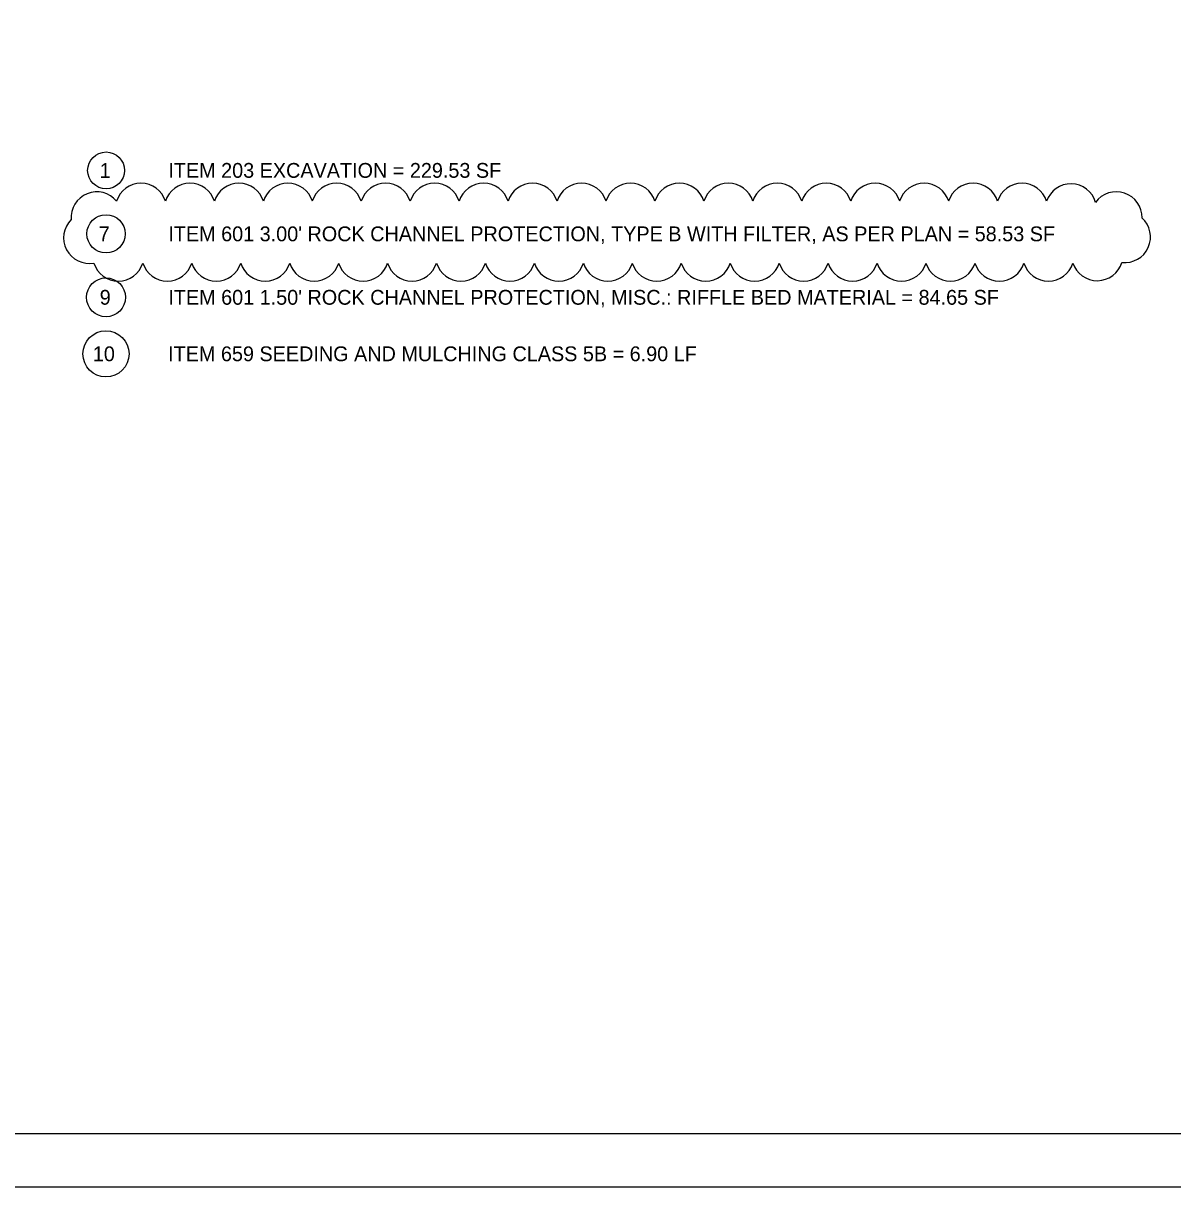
# Model space of a CAD drawing. Extents: x -179 to 34, y 0 to 22.
# Drawn here: x 12.98 to 23.85, y 0 to 11 of the extents above; entities that cross this region are included whole.
import ezdxf

# ---------------------------------------------------------------- set-up
doc = ezdxf.new("R2010")
doc.units = 0
for name, color, linetype in [('CS-ALGN-TEXT', 7, 'Continuous'), ('CS-ANNO', 7, 'Continuous'), ('CS-ANNO-MATC', 7, 'Continuous'), ('CS-ANNO-MATC-TEXT', 7, 'Continuous')]:
    doc.layers.add(name, color=color, linetype=linetype)

msp = doc.modelspace()

# ---------------------------------------------------------------- linework, layer by layer
at = {"layer": 'CS-ALGN-TEXT'}
for centre, radius, start, end in [((14.093, 9.244), 0.243, 17.5, 162.5), ((14.556, 9.244), 0.243, 17.5, 162.5), ((15.019, 9.244), 0.243, 17.5, 162.5), ((15.482, 9.244), 0.243, 17.5, 162.5), ((15.944, 9.244), 0.243, 17.5, 162.5), ((16.407, 9.244), 0.243, 17.5, 162.5), ((16.87, 9.244), 0.243, 17.5, 162.5), ((17.333, 9.244), 0.243, 17.5, 162.5), ((17.796, 9.244), 0.243, 17.5, 162.5), ((18.259, 9.244), 0.243, 17.5, 162.5), ((18.722, 9.244), 0.243, 17.5, 162.5), ((19.185, 9.244), 0.243, 17.5, 162.5), ((19.648, 9.244), 0.243, 17.5, 162.5), ((20.11, 9.244), 0.243, 17.5, 162.5), ((20.573, 9.244), 0.243, 17.5, 162.5), ((21.036, 9.244), 0.243, 17.5, 162.5), ((21.499, 9.244), 0.243, 17.5, 162.5), ((21.962, 9.244), 0.243, 17.5, 162.5), ((22.425, 9.244), 0.243, 17.5, 162.5), ((22.886, 9.239), 0.243, 16.1856, 161.1856), ((13.675, 9.163), 0.243, 39.6166, 184.6166), ((23.316, 9.164), 0.243, 359.0424, 144.0424), ((13.605, 8.972), 0.243, 135.1922, 280.1922), ((23.397, 8.979), 0.242, 263.268, 48.268), ((13.879, 8.806), 0.243, 197.5, 342.5), ((14.342, 8.806), 0.243, 197.5, 342.5), ((14.805, 8.806), 0.243, 197.5, 342.5), ((15.268, 8.806), 0.243, 197.5, 342.5), ((15.731, 8.806), 0.243, 197.5, 342.5), ((16.194, 8.806), 0.243, 197.5, 342.5), ((16.656, 8.806), 0.243, 197.5, 342.5), ((17.119, 8.806), 0.243, 197.5, 342.5), ((17.582, 8.806), 0.243, 197.5, 342.5), ((18.045, 8.806), 0.243, 197.5, 342.5), ((18.508, 8.806), 0.243, 197.5, 342.5), ((18.971, 8.806), 0.243, 197.5, 342.5), ((19.434, 8.806), 0.243, 197.5, 342.5), ((19.897, 8.806), 0.243, 197.5, 342.5), ((20.36, 8.806), 0.243, 197.5, 342.5), ((20.822, 8.806), 0.243, 197.5, 342.5), ((21.285, 8.806), 0.243, 197.5, 342.5), ((21.748, 8.806), 0.243, 197.5, 342.5), ((22.211, 8.806), 0.243, 197.5, 342.5), ((22.674, 8.806), 0.243, 197.5, 342.5), ((23.136, 8.809), 0.243, 198.1402, 343.1402)]:
    msp.add_arc(centre, radius, start, end, dxfattribs=at)
at = {"layer": 'CS-ANNO'}
msp.add_lwpolyline([(0, 0), (34, 0), (34, 22), (0, 22)], close=True, dxfattribs=at)
at = {"layer": 'CS-ANNO-MATC'}
msp.add_lwpolyline([(1.5, 21.5), (33.5, 21.5), (33.5, 0.5), (1.5, 0.5)], close=True, dxfattribs=at)
at = {"layer": 'CS-ANNO-MATC-TEXT'}
for centre, radius in [((13.763, 9.609), 0.174), ((13.763, 9.009), 0.181), ((13.763, 8.409), 0.184), ((13.762, 7.874), 0.218)]:
    msp.add_circle(centre, radius, dxfattribs=at)

# ---------------------------------------------------------------- texts
for s, p in [('ITEM 203 EXCAVATION = 229.53 SF', (14.352, 9.539)), ('1', (13.702, 9.538)), ('7', (13.693, 8.939)), ("ITEM 601 3.00' ROCK CHANNEL PROTECTION, TYPE B WITH FILTER, AS PER PLAN = 58.53 SF", (14.352, 8.939)), ('9', (13.703, 8.339)), ("ITEM 601 1.50' ROCK CHANNEL PROTECTION, MISC.: RIFFLE BED MATERIAL = 84.65 SF", (14.352, 8.339)), ('10', (13.638, 7.805)), ('ITEM 659 SEEDING AND MULCHING CLASS 5B = 6.90 LF', (14.35, 7.805))]:
    msp.add_text(s, height=0.14, dxfattribs=at).set_placement(p)

doc.saveas('drawing.dxf')
